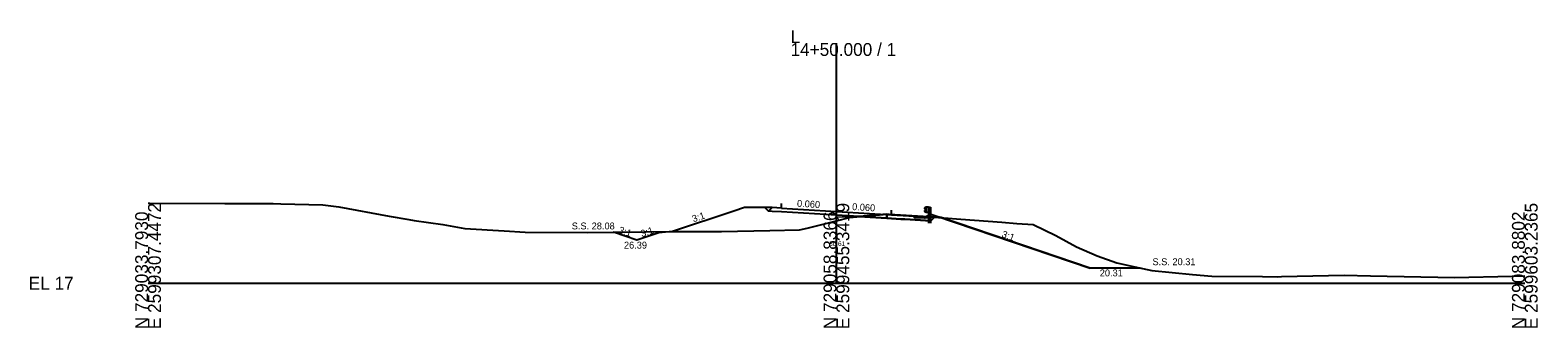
# Model space of a CAD drawing. Extents: x -26 to 3303, y -10 to 9555.
# Drawn here: x -25.7 to 302.8, y 8990.3 to 9055.1 of the extents above; entities that cross this region are included whole.
import ezdxf

# ---------------------------------------------------------------- set-up
doc = ezdxf.new("R2010")
doc.units = 0
for name, color, linetype in [('Exist Cross Section Cell', 7, 'Continuous'), ('Exist XS Center Line Elevation Label', 7, 'Continuous'), ('Exist XS Ground Line', 7, 'Continuous'), ('Prop XS Ditch Slope Text', 7, 'Continuous'), ('Prop XS Ditch Standard Text', 7, 'Continuous'), ('Prop XS Dump Level', 7, 'Continuous'), ('Prop XS Earthwork Shape', 7, 'Continuous'), ('Prop XS EOT Tick Mark', 7, 'Continuous'), ('Prop XS Finish Grade', 7, 'Continuous'), ('Prop XS Finish Grade Earthwork', 7, 'Continuous'), ('Prop XS Finish Grade Paved Shoulder', 7, 'Continuous'), ('Prop XS Finish Grade Pavement', 7, 'Continuous'), ('Prop XS Pvmt Edge Slope', 7, 'Continuous'), ('Prop XS SE Text', 7, 'Continuous'), ('Prop XS Side Slope Text', 7, 'Continuous'), ('Prop XS SS Elevation Text', 7, 'Continuous'), ('Prop XS Subgrade Earthwork', 7, 'Continuous'), ('Typical Curb CELL', 7, 'Continuous'), ('Typical Guardrail CELL', 7, 'Continuous')]:
    doc.layers.add(name, color=color, linetype=linetype)

msp = doc.modelspace()

# ---------------------------------------------------------------- linework, layer by layer
at = {"layer": 'Exist Cross Section Cell'}
for p, q in [((150, 9000), (150, 9052.26)), ((0, 9000), (150, 9000)), ((150, 9000), (300, 9000))]:
    msp.add_line(p, q, dxfattribs=at)
at = {"layer": 'Exist XS Ground Line'}
msp.add_lwpolyline([(0, 9017.42), (0.41, 9017.42), (16.73, 9017.38), (26.62, 9017.33), (27.25, 9017.33), (28.96, 9017.3), (38.09, 9017.08), (41.6, 9016.64), (52.53, 9014.62), (56.85, 9013.86), (57.95, 9013.68), (64.21, 9012.8), (69.06, 9011.94), (77.6, 9011.4), (82.17, 9011.09), (95.79, 9011.07), (101.96, 9011.08), (115.05, 9011.24), (122.03, 9011.29), (124.94, 9011.26), (135.51, 9011.51), (141.93, 9011.62), (143.65, 9012), (150, 9013.61), (152.83, 9014.33), (160.97, 9015), (161.46, 9014.97), (173.4, 9014.26), (177.12, 9013.96), (186.07, 9013.29), (189.33, 9013.01), (192.89, 9012.81), (197.84, 9010.37), (202.3, 9007.9), (206.8, 9006), (211.07, 9004.43), (215.04, 9003.54), (218.75, 9002.8), (227.61, 9001.9), (231.82, 9001.55), (242.81, 9001.44), (246.09, 9001.42), (246.98, 9001.45), (260.6, 9001.73), (266.35, 9001.63), (284.65, 9001.22), (297.24, 9001.52), (300, 9001.59)], dxfattribs=at)
at = {"layer": 'Prop XS Dump Level'}
for p, q in [((138, 9016.36), (150, 9015.64)), ((150, 9015.64), (162, 9014.92))]:
    msp.add_line(p, q, dxfattribs=at)
at = {"layer": 'Prop XS Earthwork Shape'}
for points in [[(124.94, 9011.26), (135.51, 9011.51), (141.93, 9011.62), (143.65, 9012), (150, 9013.61), (152.83, 9014.33), (154.97, 9014.51), (150, 9014.8), (138, 9015.52), (136, 9015.64), (135.21, 9015.69), (134.43, 9016.48), (130, 9016.48), (127.64, 9015.69), (114.27, 9011.23), (115.05, 9011.24), (122.03, 9011.29)], [(150, 9013.61), (152.83, 9014.33), (154.97, 9014.51), (150, 9014.8), (138, 9015.52), (136, 9015.64), (135.21, 9015.69), (134.43, 9016.48), (130, 9016.48), (127.64, 9015.69), (114.27, 9011.23), (115.05, 9011.24), (122.03, 9011.29), (124.94, 9011.26), (135.51, 9011.51), (141.93, 9011.62), (143.65, 9012)], [(154.97, 9014.51), (160.97, 9015), (160.97, 9014.15)], [(160.97, 9014.15), (160.97, 9015), (154.97, 9014.51)], [(160.97, 9015), (161.46, 9014.97), (171.38, 9014.38), (170.56, 9013.57), (164.89, 9013.91), (164, 9013.96), (162, 9014.08), (160.97, 9014.15)], [(164.89, 9013.91), (170.56, 9013.57), (171.38, 9014.38), (161.46, 9014.97), (160.97, 9015), (160.97, 9014.15), (162, 9014.08), (164, 9013.96)], [(171.38, 9014.38), (171.67, 9014.68), (172.79, 9014.3)], [(171.67, 9014.68), (172.79, 9014.3), (171.38, 9014.38)], [(211.07, 9004.43), (215.04, 9003.54), (216.2, 9003.31), (205.28, 9003.31), (172.79, 9014.3), (173.4, 9014.26), (177.12, 9013.96), (186.07, 9013.29), (189.33, 9013.01), (192.89, 9012.81), (197.84, 9010.37), (202.3, 9007.9), (206.8, 9006)], [(211.07, 9004.43), (215.04, 9003.54), (216.2, 9003.31), (205.28, 9003.31), (172.79, 9014.3), (173.4, 9014.26), (177.12, 9013.96), (186.07, 9013.29), (189.33, 9013.01), (192.89, 9012.81), (197.84, 9010.37), (202.3, 9007.9), (206.8, 9006)], [(111.27, 9010.98), (106.49, 9009.39), (101.43, 9011.08), (101.96, 9011.08), (114.27, 9011.23)], [(111.27, 9010.98), (106.49, 9009.39), (101.43, 9011.08), (101.96, 9011.08), (114.27, 9011.23)]]:
    msp.add_lwpolyline(points, close=True, dxfattribs=at)
at = {"layer": 'Prop XS EOT Tick Mark'}
for p, q in [((138, 9016.36), (138, 9017.36)), ((162, 9014.92), (162, 9015.92))]:
    msp.add_line(p, q, dxfattribs=at)
at = {"layer": 'Prop XS Finish Grade'}
for p, q in [((136, 9016.48), (134.43, 9016.48)), ((170.03, 9014.8), (170.56, 9015.05)), ((170.56, 9015.05), (171.67, 9014.68))]:
    msp.add_line(p, q, dxfattribs=at)
at = {"layer": 'Prop XS Finish Grade Earthwork'}
for p, q in [((127.64, 9015.69), (114.27, 9011.23)), ((130, 9016.48), (127.64, 9015.69)), ((134.43, 9016.48), (130, 9016.48)), ((171.67, 9014.68), (205.28, 9003.31)), ((106.49, 9009.39), (101.43, 9011.08)), ((111.27, 9010.98), (106.49, 9009.39)), ((114.27, 9011.23), (111.27, 9010.98)), ((216.2, 9003.31), (205.28, 9003.31))]:
    msp.add_line(p, q, dxfattribs=at)
at = {"layer": 'Prop XS Finish Grade Paved Shoulder'}
for p, q in [((138, 9016.36), (136, 9016.48)), ((162, 9014.92), (167, 9014.62))]:
    msp.add_line(p, q, dxfattribs=at)
at = {"layer": 'Prop XS Finish Grade Pavement'}
for p, q in [((138, 9016.36), (150, 9015.64)), ((150, 9015.64), (162, 9014.92))]:
    msp.add_line(p, q, dxfattribs=at)
at = {"layer": 'Prop XS Pvmt Edge Slope'}
for p, q in [((135.21, 9015.69), (134.43, 9016.48)), ((136, 9016.48), (135.21, 9015.69)), ((170.01, 9014.13), (170.56, 9013.57)), ((170.56, 9013.57), (171.67, 9014.68))]:
    msp.add_line(p, q, dxfattribs=at)
at = {"layer": 'Prop XS Subgrade Earthwork'}
for p, q in [((135.21, 9015.69), (134.43, 9016.48)), ((136, 9015.64), (135.21, 9015.69)), ((138, 9015.52), (136, 9015.64)), ((150, 9014.8), (138, 9015.52)), ((160.97, 9014.15), (160.97, 9015)), ((160.97, 9014.15), (160.97, 9015)), ((160.97, 9014.15), (150, 9014.8)), ((160.97, 9014.15), (162, 9014.08)), ((162, 9014.08), (164, 9013.96)), ((164, 9013.96), (164.89, 9013.91)), ((164.89, 9013.91), (170.56, 9013.57)), ((170.56, 9013.57), (171.67, 9014.68))]:
    msp.add_line(p, q, dxfattribs=at)
at = {"layer": 'Typical Curb CELL'}
for p, q in [((166.99, 9014.2), (167, 9014.61)), ((170.01, 9014.13), (166.99, 9014.2)), ((167, 9014.62), (167, 9014.62)), ((167.01, 9014.62), (169.33, 9014.48)), ((167.23, 9014.35), (167.32, 9014.46)), ((167.35, 9014.35), (167.23, 9014.35)), ((167.32, 9014.46), (167.35, 9014.35)), ((167.99, 9014.28), (168.06, 9014.39)), ((168.16, 9014.31), (167.99, 9014.28)), ((168.06, 9014.39), (168.16, 9014.31)), ((168.48, 9014.32), (168.57, 9014.43)), ((168.6, 9014.32), (168.48, 9014.32)), ((168.57, 9014.43), (168.6, 9014.32)), ((169.24, 9014.25), (169.31, 9014.36)), ((169.41, 9014.28), (169.24, 9014.25)), ((169.31, 9014.36), (169.41, 9014.28)), ((169.33, 9014.48), (170.03, 9014.8)), ((169.83, 9014.47), (169.84, 9014.38)), ((169.98, 9014.42), (169.83, 9014.47)), ((169.84, 9014.38), (169.98, 9014.42)), ((170.01, 9014.13), (170.03, 9014.8))]:
    msp.add_line(p, q, dxfattribs=at)
for centre in [(167.09, 9014.44), (167.13, 9014.56), (167.49, 9014.48), (167.55, 9014.3), (167.6, 9014.26), (167.64, 9014.39), (167.71, 9014.38), (167.76, 9014.41), (167.81, 9014.3), (168, 9014.33), (168.21, 9014.31), (168.23, 9014.36), (168.24, 9014.42), (168.29, 9014.27), (168.39, 9014.32), (168.48, 9014.33), (168.6, 9014.27), (168.8, 9014.27), (168.85, 9014.23), (168.89, 9014.36), (169.01, 9014.38), (169.06, 9014.27), (169.25, 9014.3), (169.28, 9014.2), (169.46, 9014.28), (169.48, 9014.33), (169.73, 9014.29), (169.85, 9014.24), (169.95, 9014.51)]:
    msp.add_circle(centre, 0.00802, dxfattribs=at)
msp.add_arc((167.01, 9014.61), 0.0104, 86.5213, 178.5693, dxfattribs=at)
at = {"layer": 'Typical Guardrail CELL'}
for p, q in [((169.53, 9016.58), (169.24, 9016.38)), ((169.53, 9016.05), (169.24, 9016.25)), ((169.53, 9015.96), (169.24, 9015.75)), ((169.53, 9015.42), (169.24, 9015.63)), ((170.03, 9016.58), (169.53, 9016.58)), ((169.53, 9016.58), (169.53, 9015.42)), ((169.53, 9016), (169.53, 9016.05)), ((169.53, 9016), (169.53, 9015.96)), ((170.03, 9015.42), (169.53, 9015.42)), ((170.03, 9016.58), (170.03, 9014.1)), ((170.03, 9016.58), (170.53, 9016.58)), ((170.53, 9016.58), (170.53, 9014.1)), ((170.03, 9014.1), (170.53, 9014.1)), ((170.03, 9014.1), (170.03, 9013.09)), ((170.53, 9014.1), (170.53, 9013.09))]:
    msp.add_line(p, q, dxfattribs=at)
for centre, start, end in [((169.29, 9016.32), 125.003, 235.0112), ((169.29, 9015.69), 125.0059, 235.0366)]:
    msp.add_arc(centre, 0.0776, start, end, dxfattribs=at)

# ---------------------------------------------------------------- texts
at = {"layer": 'Exist Cross Section Cell'}
for s, p in [('L', (140, 9052.26)), ('14+50.000 / 1', (140, 9049.46)), ('EL 17', (-26, 8998.6))]:
    msp.add_text(s, height=2.8, dxfattribs=at).set_placement(p)
for s, p in [('N 729033.7930', (0, 8990)), ('E 2599307.4472', (2.8, 8990)), ('N 729058.8366', (150, 8990)), ('E 2599455.3419', (152.8, 8990)), ('N 729083.8802', (300, 8990)), ('E 2599603.2365', (302.8, 8990))]:
    msp.add_text(s, height=2.8, rotation=90, dxfattribs=at).set_placement(p)
at = {"layer": 'Exist XS Center Line Elevation Label'}
msp.add_text('30.61', height=1, dxfattribs=at).set_placement((148.43, 9008.11))
at = {"layer": 'Prop XS Ditch Slope Text'}
msp.add_text('3:1', height=1.5, rotation=340.5558, dxfattribs=at).set_placement((185.89, 9010.08))
at = {"layer": 'Prop XS Ditch Standard Text'}
msp.add_text('20.31', height=1.5, dxfattribs=at).set_placement((207.38, 9001.5))
at = {"layer": 'Prop XS Dump Level'}
for s, height, p in [('Case1', 0.04, (130, 9016.44)), ('Eop', 0.3, (160.97, 9014.7)), ('Eop', 0.3, (160.97, 9014.7)), ('Case1', 0.04, (170, 9014.28)), ('Case1', 0.04, (173, 9014.04))]:
    msp.add_text(s, height=height, dxfattribs=at).set_placement(p)
at = {"layer": 'Prop XS SE Text'}
for p in [(141.38, 9016.65), (153.38, 9015.93)]:
    msp.add_text('0.060', height=1.5, rotation=356.5664, dxfattribs=at).set_placement(p)
at = {"layer": 'Prop XS Side Slope Text'}
for rotation, p in [(18.4349, (118.84, 9013.24)), (341.0185, (102.41, 9010.99)), (18.4349, (107.63, 9010.01))]:
    msp.add_text('3:1', height=1.5, rotation=rotation, dxfattribs=at).set_placement(p)
at = {"layer": 'Prop XS SS Elevation Text'}
for s, p in [('S.S. 28.08', (92.32, 9011.71)), ('26.39', (103.7, 9007.54)), ('S.S. 20.31', (218.87, 9003.93))]:
    msp.add_text(s, height=1.5, dxfattribs=at).set_placement(p)

doc.saveas('drawing.dxf')
